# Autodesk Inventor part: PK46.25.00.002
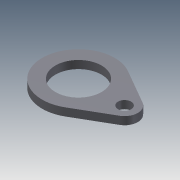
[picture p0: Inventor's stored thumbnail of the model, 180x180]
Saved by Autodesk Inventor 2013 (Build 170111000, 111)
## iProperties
Created: 2005-05
Part Number: PK46.25.00.002
Material: Steel, Mild
Document SubType Name: Modeling
Designer: PVitaliy
Manufacturer: Standard
Standards Organization: Custom
Density: 7.86 g/cm^3
Author: PVitaliy
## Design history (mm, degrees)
sketch "Эскиз2"
  geometry: L1 (0, 0)-(70, 0); L2 (27.5, 47.631)-(80, 17.321); L3 (80, -17.321)-(27.5, -47.631); C1 r 35 at (0, 0); C2 r 10 at (70, 0); A1 r 55 centre (0, 0) between (27.5, 47.631) and (27.5, -47.631); A2 r 20 centre (70, 0) between (80, -17.321) and (80, 17.321)
  constraints: 6 end point, 4 centre point, 4 point on circle, 4 tangent, 3 coincident, 1 horizontal, 1 other
  dimensions: "d0" = 70 distance of L1.start L1.end; "d1" = 55 radius of A1; "d2" = 70 diameter of C1; "d3" = 20 radius of A2; "d4" = 20 diameter of C2
extrude "Выдавливание1" new body sketch "Эскиз2" distance "d5" = 12; taper "d6" = 0 deg
body "Solid1"
